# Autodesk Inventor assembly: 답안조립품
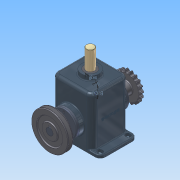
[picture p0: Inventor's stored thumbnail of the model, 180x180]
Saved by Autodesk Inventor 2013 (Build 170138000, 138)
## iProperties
Created: 2015-03
Part Number: 답안조립품
Document SubType Name: Assembly
Designer: Administrator
Mass: 8579 g
Surface Area: 4386.42 cm^2
Volume: 1982.5 cm^3
Density: 4.32736 g/cm^3
Author: Administrator
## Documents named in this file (15)
- C:\Documents and Settings\Administrator\바탕 화면\350305V1035\답안조립품.iam
- C:\Documents and Settings\Administrator\바탕 화면\350305V1035\본체.ipt
- C:\Documents and Settings\Administrator\바탕 화면\350305V1035\베어링 6205.ipt
- C:\Documents and Settings\Administrator\바탕 화면\350305V1035\편심축.ipt
- C:\Documents and Settings\Administrator\바탕 화면\350305V1035\멈춤링.ipt
- C:\Documents and Settings\Administrator\바탕 화면\350305V1035\키 8x8.ipt
- C:\Documents and Settings\Administrator\바탕 화면\350305V1035\커버.ipt
- C:\Documents and Settings\Administrator\바탕 화면\350305V1035\오일실.ipt
- C:\Documents and Settings\Administrator\바탕 화면\350305V1035\M4x0.5.ipt
- C:\Documents and Settings\Administrator\바탕 화면\350305V1035\슬라이드.ipt
- C:\Documents and Settings\Administrator\바탕 화면\350305V1035\부시.ipt
- C:\Documents and Settings\Administrator\바탕 화면\350305V1035\V-벨트풀리.ipt
- C:\Documents and Settings\Administrator\바탕 화면\350305V1035\체인 스프로킷.ipt
- C:\Documents and Settings\Administrator\바탕 화면\350305V1035\멈춤나사 M5x0.5.ipt
- C:\Documents and Settings\Administrator\바탕 화면\350305V1035\7-가변스프링.ipt
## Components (9 placed, 4 different names)
1. V-벨트풀리:1 — 플러쉬:3, 각도:4
2. 5-체인 스프로킷:1 — 플러쉬:4, 각도:5
3. 7-가변스프링:1
4. M4x0.5:1
5. M4x0.5:3
6. M4x0.5:4
7. M4x0.5:2
8. M4x0.5:5
9. M4x0.5:6
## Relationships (4: Flush 2, Angle 2)
- 플러쉬:3 [Flush]: V-벨트풀리:1
- 각도:4 [Angle]: V-벨트풀리:1
- 플러쉬:4 [Flush]: 5-체인 스프로킷:1
- 각도:5 [Angle]: 5-체인 스프로킷:1
